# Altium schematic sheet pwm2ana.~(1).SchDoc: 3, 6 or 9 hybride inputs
size A4; Revision: V0.1; SheetNumber: 1; SheetTotal: 1; PageSetup: Record=PageOptions¦CenterHorizontal=True¦CenterVertical=True¦PrintScale=1.00¦XCorrection=1.00¦YCorrection=1.00¦PrintKind=2¦BorderSize=5000000¦LeftOffset=0¦BottomOffset=0¦Orientation=2¦PaperLength=1000¦PaperWidth=1000¦Scale=100¦PaperSource=7¦PrintQuality=-4¦MediaType=1¦DitherType=10¦PaperKind=A4¦PrintScaleMode=1
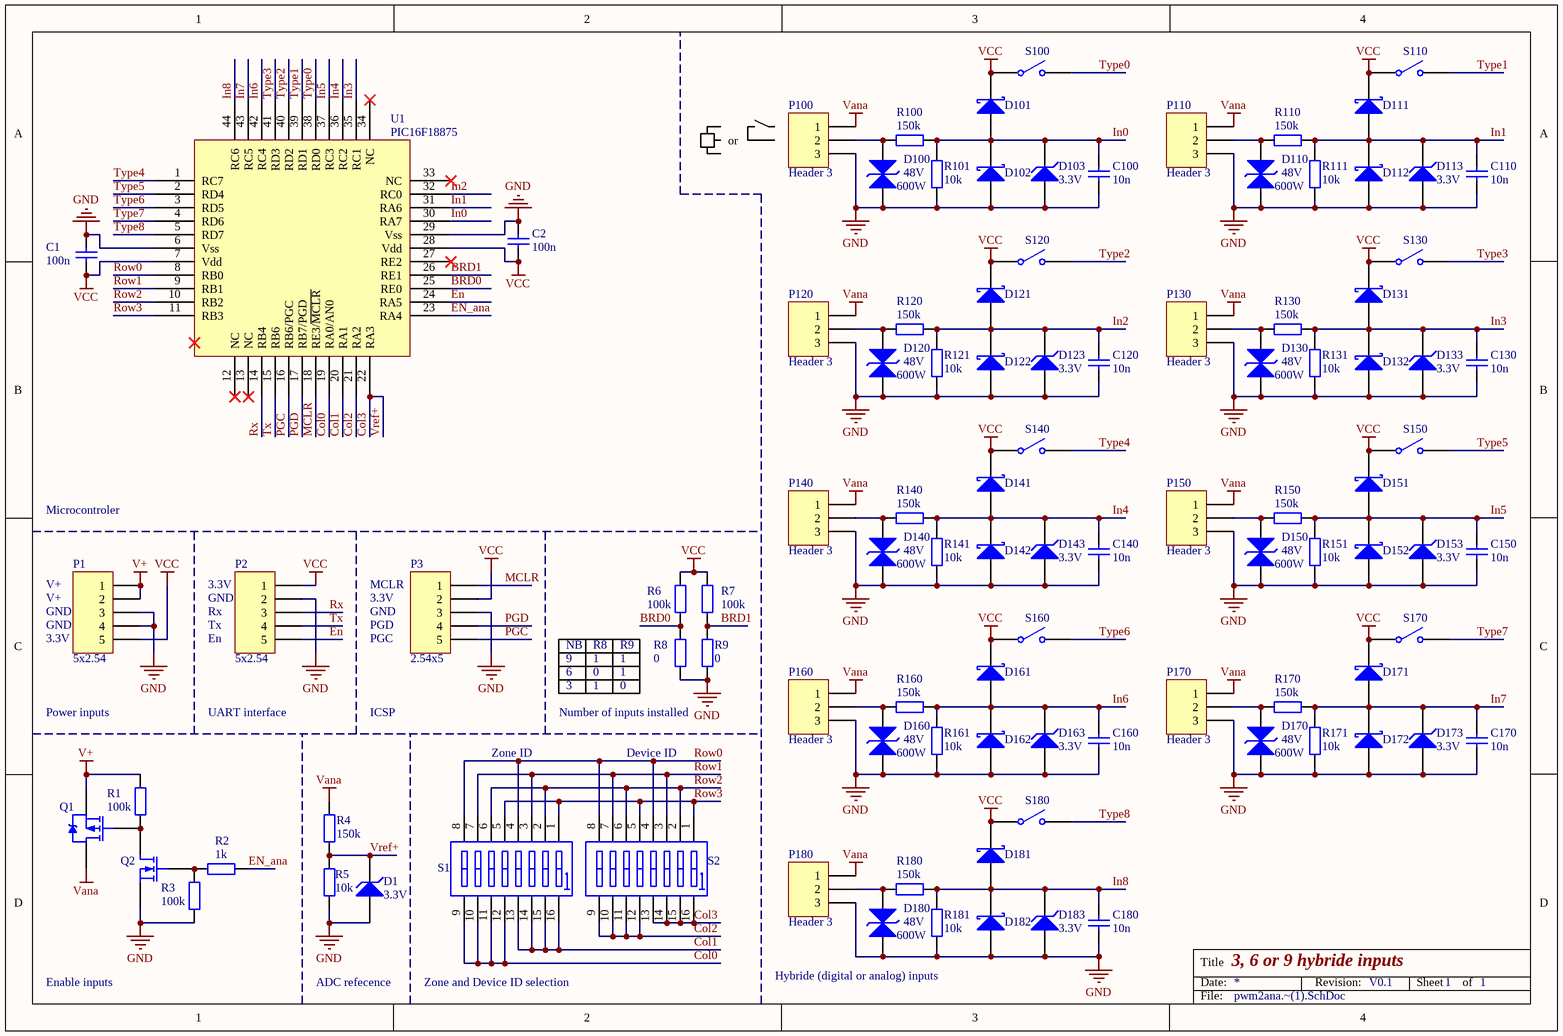
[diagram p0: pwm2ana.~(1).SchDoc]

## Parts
C1  100n  [C0402]
C2  100n  [C0402]
C100  10n  [C0402]
C110  10n  [C0402]
C120  10n  [C0402]
C130  10n  [C0402]
C140  10n  [C0402]
C150  10n  [C0402]
C160  10n  [C0402]
C170  10n  [C0402]
C180  10n  [C0402]
D1  3.3V  [DIODE-0.7]
D100  Vrm: 48V  power: 600W
D101  Diode BAS70  [SOT-23_N]  (value not drawn)
D102  Diode BAS70  [SOT-23_N]  (value not drawn)
D103  3.3V  [DIODE-0.7]
D110  Vrm: 48V  power: 600W
D111  Diode BAS70  [SOT-23_N]  (value not drawn)
D112  Diode BAS70  [SOT-23_N]  (value not drawn)
D113  3.3V  [DIODE-0.7]
D120  Vrm: 48V  power: 600W
D121  Diode BAS70  [SOT-23_N]  (value not drawn)
D122  Diode BAS70  [SOT-23_N]  (value not drawn)
D123  3.3V  [DIODE-0.7]
D130  Vrm: 48V  power: 600W
D131  Diode BAS70  [SOT-23_N]  (value not drawn)
D132  Diode BAS70  [SOT-23_N]  (value not drawn)
D133  3.3V  [DIODE-0.7]
D140  Vrm: 48V  power: 600W
D141  Diode BAS70  [SOT-23_N]  (value not drawn)
D142  Diode BAS70  [SOT-23_N]  (value not drawn)
D143  3.3V  [DIODE-0.7]
D150  Vrm: 48V  power: 600W
D151  Diode BAS70  [SOT-23_N]  (value not drawn)
D152  Diode BAS70  [SOT-23_N]  (value not drawn)
D153  3.3V  [DIODE-0.7]
D160  Vrm: 48V  power: 600W
D161  Diode BAS70  [SOT-23_N]  (value not drawn)
D162  Diode BAS70  [SOT-23_N]  (value not drawn)
D163  3.3V  [DIODE-0.7]
D170  Vrm: 48V  power: 600W
D171  Diode BAS70  [SOT-23_N]  (value not drawn)
D172  Diode BAS70  [SOT-23_N]  (value not drawn)
D173  3.3V  [DIODE-0.7]
D180  Vrm: 48V  power: 600W
D181  Diode BAS70  [SOT-23_N]  (value not drawn)
D182  Diode BAS70  [SOT-23_N]  (value not drawn)
D183  3.3V  [DIODE-0.7]
P1  5x2.54  [HDR1X5]
P2  5x2.54  [HDR1X5]
P3  2.54x5  [HDR1X5]
P100  Header 3  [HDR1X3]
P110  Header 3  [HDR1X3]
P120  Header 3  [HDR1X3]
P130  Header 3  [HDR1X3]
P140  Header 3  [HDR1X3]
P150  Header 3  [HDR1X3]
P160  Header 3  [HDR1X3]
P170  Header 3  [HDR1X3]
P180  Header 3  [HDR1X3]
Q1  PMOS-2  [TO-220AB]  (value not drawn)
Q2  MOSFET-N  [E3]  (value not drawn)
R1  100k  [R0402]
R2  1k  [R0402]
R3  100k  [R0402]
R4  150k  [R0402]
R5  10k  [R0402]
R6  100k  [R0402]
R7  100k  [R0402]
R8  0  [R0402]
R9  0  [R0402]
R100  150k  [R0402]
R101  10k  [R0402]
R110  150k  [R0402]
R111  10k  [R0402]
R120  150k  [R0402]
R121  10k  [R0402]
R130  150k  [R0402]
R131  10k  [R0402]
R140  150k  [R0402]
R141  10k  [R0402]
R150  150k  [R0402]
R151  10k  [R0402]
R160  150k  [R0402]
R161  10k  [R0402]
R170  150k  [R0402]
R171  10k  [R0402]
R180  150k  [R0402]
R181  10k  [R0402]
S1  SW DIP-8  [DIP_SW_8WAY_SMD]  (value not drawn)
S2  SW DIP-8  [DIP_SW_8WAY_SMD]  (value not drawn)
S100  SW-SPST  [SPST-2]  (value not drawn)
S110  SW-SPST  [SPST-2]  (value not drawn)
S120  SW-SPST  [SPST-2]  (value not drawn)
S130  SW-SPST  [SPST-2]  (value not drawn)
S140  SW-SPST  [SPST-2]  (value not drawn)
S150  SW-SPST  [SPST-2]  (value not drawn)
S160  SW-SPST  [SPST-2]  (value not drawn)
S170  SW-SPST  [SPST-2]  (value not drawn)
S180  SW-SPST  [SPST-2]  (value not drawn)
U1  PIC16F18875  [TQFP-44N]

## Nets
GND: C1.2 C2.2 C100.1 C110.1 C120.1 C130.1 C140.1 C150.1 C160.1 C170.1 C180.1 D1.1(A) D100.A D102.1(A) D103.1(A) D110.A D112.1(A) D113.1(A) D120.A D122.1(A) D123.1(A) D130.A D132.1(A) D133.1(A) D140.A D142.1(A) D143.1(A) D150.A D152.1(A) D153.1(A) D160.A D162.1(A) D163.1(A) D170.A D172.1(A) D173.1(A) D180.A D182.1(A) D183.1(A) P1.3 P1.4 P2.2 P3.3 P100.3 P110.3 P120.3 P130.3 P140.3 P150.3 P160.3 P170.3 P180.3 Q2.3(S) R3.2 R5.2 R8.2 R9.2 R101.2 R111.2 R121.2 R131.2 R141.2 R151.2 R161.2 R171.2 R181.2 U1.6(Vss) U1.29(Vss)
V+: P1.1 P1.2 Q1.3(S) R1.1
Vana: P100.1 P110.1 P120.1 P130.1 P140.1 P150.1 P160.1 P170.1 P180.1 Q1.2(D) R4.1
VCC: C1.1 C2.1 D101.3(K) D111.3(K) D121.3(K) D131.3(K) D141.3(K) D151.3(K) D161.3(K) D171.3(K) D181.3(K) P1.5 P2.1 P3.2 R6.1 R7.1 S100.1(COMMON) S110.1(COMMON) S120.1(COMMON) S130.1(COMMON) S140.1(COMMON) S150.1(COMMON) S160.1(COMMON) S170.1(COMMON) S180.1(COMMON) U1.7(Vdd) U1.28(Vdd)
BRD0: R6.2 R8.1 U1.25(RE0)
BRD1: R7.2 R9.1 U1.26(RE1)
Col0: S1.9(B8) S1.10(B7) S1.11(B6) S1.12(B5) U1.19(RA0/AN0)
Col1: S1.13(B4) S1.14(B3) S1.15(B2) S1.16(B1) U1.20(RA1)
Col2: S2.9(B8) S2.10(B7) S2.11(B6) S2.12(B5) U1.21(RA2)
Col3: D1.2(K) R4.2 R5.1 S2.13(B4) S2.14(B3) S2.15(B2) S2.16(B1) U1.22(RA3)  [also labelled Vref+]
En: P2.5 U1.24(RA5)
EN_ana: R2.2 U1.23(RA4)
In0: C100.2 D101.1(A) D102.3(K) D103.2(K) R100.2 R101.1 U1.30(RA7)
In1: C110.2 D111.1(A) D112.3(K) D113.2(K) R110.2 R111.1 U1.31(RA6)
In2: C120.2 D121.1(A) D122.3(K) D123.2(K) R120.2 R121.1 U1.32(RC0)
In3: C130.2 D131.1(A) D132.3(K) D133.2(K) R130.2 R131.1 U1.35(RC1)
In4: C140.2 D141.1(A) D142.3(K) D143.2(K) R140.2 R141.1 U1.36(RC2)
In5: C150.2 D151.1(A) D152.3(K) D153.2(K) R150.2 R151.1 U1.37(RC3)
In6: C160.2 D161.1(A) D162.3(K) D163.2(K) R160.2 R161.1 U1.42(RC4)
In7: C170.2 D171.1(A) D172.3(K) D173.2(K) R170.2 R171.1 U1.43(RC5)
In8: C180.2 D181.1(A) D182.3(K) D183.2(K) R180.2 R181.1 U1.44(RC6)
MCLR: P3.1 U1.18(RE3/~{MCLR})
PGC: P3.5 U1.16(RB6/PGC)
PGD: P3.4 U1.17(RB7/PGD)
Row0: S1.4(A4) S1.8(A8) S2.4(A4) S2.8(A8) U1.8(RB0)
Row1: S1.3(A3) S1.7(A7) S2.3(A3) S2.7(A7) U1.9(RB1)
Row2: S1.2(A2) S1.6(A6) S2.2(A2) S2.6(A6) U1.10(RB2)
Row3: S1.1(A1) S1.5(A5) S2.1(A1) S2.5(A5) U1.11(RB3)
Rx: P2.3 U1.14(RB4)
Tx: P2.4 U1.15(RB6)
Type0: S100.2(NO) U1.38(RD0)
Type1: S110.2(NO) U1.39(RD1)
Type2: S120.2(NO) U1.40(RD2)
Type3: S130.2(NO) U1.41(RD3)
Type4: S140.2(NO) U1.1(RC7)
Type5: S150.2(NO) U1.2(RD4)
Type6: S160.2(NO) U1.3(RD5)
Type7: S170.2(NO) U1.4(RD6)
Type8: S180.2(NO) U1.5(RD7)
NetD100_K: D100.K P100.2 R100.1
NetD110_K: D110.K P110.2 R110.1
NetD120_K: D120.K P120.2 R120.1
NetD130_K: D130.K P130.2 R130.1
NetD140_K: D140.K P140.2 R140.1
NetD150_K: D150.K P150.2 R150.1
NetD160_K: D160.K P160.2 R160.1
NetD170_K: D170.K P170.2 R170.1
NetD180_K: D180.K P180.2 R180.1
NetQ1_1: Q1.1(G) Q2.1(D) R1.2
NetQ2_2: Q2.2(G) R2.1 R3.1

Not connected (* = marked no-connect by the designer): U1 12(NC)* 13(NC)* 27(RE2)* 33(NC)* 34(NC)*

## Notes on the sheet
- or
- Microcontroler
- V+
- (near P1) GND
- (near P1) 3.3V
- (near P2) GND
- (near P2) 3.3V
- Rx
- Tx
- En
- MCLR
- GND
- 3.3V
- PGD
- PGC
- NB
- R8
- R9
- Power inputs
- UART interface
- ICSP
- Number of inputs installed
- 3
- 6
- 9
- 0
- 1
- Zone ID
- Device ID
- Enable inputs
- ADC refecence
- Zone and Device ID selection
- Hybride (digital or analog) inputs

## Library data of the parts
C1 C2 C100 C110 C120 C130 C140 C150 C160 C170 C180 = Cap: Capacitor; Manufacturer: PHILIPS COMPONENTS; Manufacturer  Part Number: C-0603
D1 D103 D113 D123 D133 D143 D153 D163 D173 D183 = D Zener: Zener Diode
D100 D110 D120 D130 D140 D150 D160 D170 D180 = Diode TVS: TVS diode
D101 D102 D111 D112 D121 D122 D131 D132 D141 D142 D151 D152 D161 D162 D171 D172 D181 D182 = Diode BAS70: Silicon AF Schottky Diode for High-Speed Switching; Note: Pin 2 is not connected and not drawn.
P1-P3 = Header 5: Header, 5-Pin
P100 P110 P120 P130 P140 P150 P160 P170 P180 = Header 3: Header, 3-Pin
Q1 = PMOS-2: P-Channel Power MOSFET; Note: Pin 4 not drawn and electrically connected to Pin 2.
Q2 = MOSFET-N: N-Channel MOSFET
R1-R9 R100 R101 R110 R111 R120 R121 R130 R131 R140 R141 R150 R151 R160 R161 R170 R171 R180 R181 = Res2: Resistor; Manufacturer: MULTICOMP
S1 S2 = SW DIP-8: DIP Switch, 8 Position, SPST
S100 S110 S120 S130 S140 S150 S160 S170 S180 = SW-SPST: Single-Pole, Single-Throw Switch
